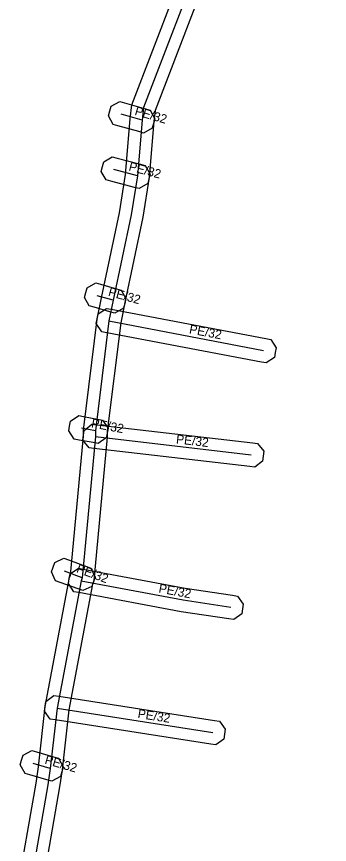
# Model space of a CAD drawing. Extents: x -772893 to -772575, y -1033735 to -1033288.
# Drawn here: x -772822.7 to -772796.5, y -1033432.5 to -1033363.2 of the extents above; entities that cross this region are included whole.
import ezdxf

# ---------------------------------------------------------------- set-up
doc = ezdxf.new("R2010")
doc.units = 0
for name, color, linetype in [('1', 7, 'Continuous'), ('24', 7, 'Continuous'), ('30', 7, 'Continuous')]:
    doc.layers.add(name, color=color, linetype=linetype)

msp = doc.modelspace()

# ---------------------------------------------------------------- linework, layer by layer
at = {"layer": '1'}
for points in [[(-772822.714, -1033436.766), (-772821.087, -1033427.39), (-772820.882, -1033426.03), (-772820.32, -1033420.962), (-772818.286, -1033410.176), (-772818.203, -1033409.96), (-772817.12, -1033398.324), (-772817.12, -1033397.828), (-772815.968, -1033388.52), (-772815.61, -1033386.739), (-772814.113, -1033379.607), (-772813.593, -1033376.398), (-772813.205, -1033371.757), (-772813.058, -1033370.567), (-772807.808, -1033356.817)], [(-772805.952, -1033357.563), (-772811.102, -1033371.053), (-772811.215, -1033371.963), (-772811.607, -1033376.642), (-772812.147, -1033379.973), (-772813.65, -1033387.141), (-772813.992, -1033388.84), (-772815.12, -1033397.952), (-772815.12, -1033398.416), (-772816.237, -1033410.42), (-772816.354, -1033410.724), (-772818.34, -1033421.258), (-772818.898, -1033426.29), (-772819.113, -1033427.71), (-772820.706, -1033436.894)]]:
    msp.add_lwpolyline(points, dxfattribs=at)
for points in [[(-772812.088, -1033372.935), (-772812.486, -1033372.821), (-772814.226, -1033372.321), (-772814.624, -1033372.207), (-772815.025, -1033371.482), (-772814.911, -1033371.084), (-772814.797, -1033370.686), (-772814.072, -1033370.285), (-772813.674, -1033370.399), (-772811.934, -1033370.899), (-772811.536, -1033371.013), (-772811.135, -1033371.738), (-772811.249, -1033372.136), (-772811.363, -1033372.534)], [(-772812.456, -1033377.593), (-772812.856, -1033377.487), (-772814.816, -1033376.967), (-772815.217, -1033376.861), (-772815.633, -1033376.144), (-772815.527, -1033375.744), (-772815.421, -1033375.343), (-772814.704, -1033374.927), (-772814.304, -1033375.033), (-772812.344, -1033375.553), (-772811.943, -1033375.659), (-772811.527, -1033376.376), (-772811.633, -1033376.776), (-772811.739, -1033377.177)], [(-772814.499, -1033388.014), (-772814.898, -1033387.903), (-772816.228, -1033387.533), (-772816.627, -1033387.422), (-772817.034, -1033386.701), (-772816.923, -1033386.302), (-772816.812, -1033385.903), (-772816.091, -1033385.496), (-772815.692, -1033385.607), (-772814.362, -1033385.977), (-772813.963, -1033386.088), (-772813.556, -1033386.809), (-772813.667, -1033387.208), (-772813.778, -1033387.607)], [(-772815.2, -1033387.621), (-772814.793, -1033387.698), (-772801.853, -1033390.158), (-772801.446, -1033390.235), (-772800.981, -1033390.92), (-772801.058, -1033391.327), (-772801.135, -1033391.734), (-772801.82, -1033392.199), (-772802.227, -1033392.122), (-772815.167, -1033389.662), (-772815.574, -1033389.585), (-772816.039, -1033388.9), (-772815.962, -1033388.493), (-772815.885, -1033388.086)], [(-772815.898, -1033398.95), (-772816.305, -1033398.873), (-772817.475, -1033398.653), (-772817.882, -1033398.576), (-772818.35, -1033397.892), (-772818.273, -1033397.485), (-772818.196, -1033397.078), (-772817.512, -1033396.61), (-772817.105, -1033396.687), (-772815.935, -1033396.907), (-772815.528, -1033396.984), (-772815.06, -1033397.668), (-772815.137, -1033398.075), (-772815.214, -1033398.482)], [(-772816.416, -1033397.329), (-772816.004, -1033397.377), (-772802.954, -1033398.897), (-772802.543, -1033398.945), (-772802.029, -1033399.594), (-772802.077, -1033400.006), (-772802.125, -1033400.417), (-772802.774, -1033400.931), (-772803.186, -1033400.883), (-772816.236, -1033399.363), (-772816.647, -1033399.315), (-772817.161, -1033398.666), (-772817.113, -1033398.254), (-772817.065, -1033397.843)], [(-772817.177, -1033411.271), (-772817.566, -1033411.128), (-772819.056, -1033410.578), (-772819.445, -1033410.435), (-772819.791, -1033409.683), (-772819.648, -1033409.294), (-772819.505, -1033408.905), (-772818.753, -1033408.559), (-772818.364, -1033408.702), (-772816.874, -1033409.252), (-772816.485, -1033409.395), (-772816.139, -1033410.147), (-772816.282, -1033410.536), (-772816.425, -1033410.925)], [(-772817.543, -1033409.391), (-772817.136, -1033409.467), (-772808.593, -1033411.064), (-772804.641, -1033411.661), (-772804.231, -1033411.723), (-772803.739, -1033412.39), (-772803.801, -1033412.799), (-772803.863, -1033413.209), (-772804.53, -1033413.701), (-772804.939, -1033413.639), (-772808.927, -1033413.036), (-772817.504, -1033411.433), (-772817.911, -1033411.357), (-772818.379, -1033410.673), (-772818.303, -1033410.266), (-772818.227, -1033409.859)], [(-772819.585, -1033420.058), (-772819.176, -1033420.122), (-772806.146, -1033422.152), (-772805.737, -1033422.216), (-772805.248, -1033422.885), (-772805.312, -1033423.294), (-772805.376, -1033423.703), (-772806.045, -1033424.192), (-772806.454, -1033424.128), (-772819.484, -1033422.098), (-772819.893, -1033422.034), (-772820.382, -1033421.365), (-772820.318, -1033420.956), (-772820.254, -1033420.547)], [(-772819.772, -1033427.236), (-772820.17, -1033427.12), (-772821.61, -1033426.7), (-772822.008, -1033426.584), (-772822.406, -1033425.858), (-772822.29, -1033425.46), (-772822.174, -1033425.062), (-772821.448, -1033424.664), (-772821.05, -1033424.78), (-772819.61, -1033425.2), (-772819.212, -1033425.316), (-772818.814, -1033426.042), (-772818.93, -1033426.44), (-772819.046, -1033426.838)]]:
    msp.add_lwpolyline(points, close=True, dxfattribs=at)
at = {"layer": '24'}
for points in [[(-772796.53, -1033335.21), (-772796.549, -1033335.243), (-772805.22, -1033353.26), (-772806.88, -1033357.19), (-772812.079, -1033370.809), (-772812.21, -1033371.86), (-772812.6, -1033376.52), (-772813.129, -1033379.789), (-772814.63, -1033386.94), (-772814.98, -1033388.68), (-772816.12, -1033397.89), (-772816.12, -1033398.37), (-772817.22, -1033410.19), (-772817.32, -1033410.45), (-772819.33, -1033421.11), (-772819.89, -1033426.16), (-772820.099, -1033427.549), (-772821.71, -1033436.83)], [(-772812.21, -1033371.86), (-772813.95, -1033371.36)], [(-772812.6, -1033376.52), (-772814.56, -1033376)], [(-772814.63, -1033386.94), (-772815.96, -1033386.57)], [(-772814.98, -1033388.68), (-772802.04, -1033391.14)], [(-772816.12, -1033397.89), (-772817.29, -1033397.67)], [(-772816.12, -1033398.37), (-772803.07, -1033399.89)], [(-772817.22, -1033410.19), (-772818.71, -1033409.64)], [(-772817.32, -1033410.45), (-772808.759, -1033412.049), (-772804.79, -1033412.65)], [(-772819.33, -1033421.11), (-772806.3, -1033423.14)], [(-772819.89, -1033426.16), (-772821.33, -1033425.74)]]:
    msp.add_lwpolyline(points, dxfattribs=at)

# ---------------------------------------------------------------- texts
at = {"layer": '30'}
for rotation, p in [(343.96766, (-772812.88, -1033371.41)), (345.14139, (-772813.38, -1033376.06)), (344.45367, (-772815.095, -1033386.555)), (349.23605, (-772808.31, -1033389.71)), (349.35078, (-772816.505, -1033397.58)), (353.3564, (-772809.395, -1033398.93)), (339.73951, (-772817.765, -1033409.715)), (349.42035, (-772810.866, -1033411.418)), (351.14483, (-772812.615, -1033421.925)), (343.7398, (-772820.41, -1033425.75))]:
    msp.add_text('PE/32', height=0.75, rotation=rotation, dxfattribs=at).set_placement(p)

doc.saveas('drawing.dxf')
